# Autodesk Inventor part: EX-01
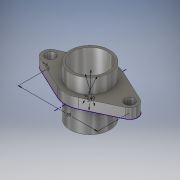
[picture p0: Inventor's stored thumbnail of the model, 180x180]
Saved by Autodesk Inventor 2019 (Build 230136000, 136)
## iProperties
Created: 2018-08
Part Number: EX-01
Material: Nickel-Copper Alloy 400
Description: 123456
Document SubType Name: Modeling
Designer: Power User
Mass: 162915 g
Surface Area: 10619 cm^2
Volume: 18450.2 cm^3
Density: 8.83 g/cm^3
Appearance: Chrome - Polished
Title: GEAR
Author: Power User
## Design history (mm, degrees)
sketch "Sketch6"
  geometry: L1 (0, 36.463)-(0, -36.463); L2 (-43.4, 7.242)-(-10.625, 22.63); L3 (-40, 0)-(40, 0); L4 (-43.4, -7.242)-(-10.625, -22.63); L5 (10.625, 22.63)-(43.4, 7.242); L6 (10.625, -22.63)-(43.4, -7.242); C1 r 17.5 at (0, 0); C2 r 20 at (0, 0); C3 r 5 at (-40, 0); C4 r 5 at (40, 0); A1 r 25 centre (0, 0) between (-10.625, 22.63) and (-10.625, -22.63); A2 r 8 centre (-40, 0) between (-43.4, 7.242) and (-43.4, -7.242); A3 r 8 centre (40, 0) between (43.4, 7.242) and (43.4, -7.242); 2 further points
  constraints: 12 end point, 8 point on circle, 8 tangent, 7 centre point, 6 coincident, 2 equal radius, 2 horizontal alignment, 1 horizontal, 1 midpoint, 1 symmetric about line, 1 vertical
  dimensions: "d49" = 35 diameter of C1; "d50" = 40 diameter of C2; "d51" = 50 diameter of A1; "d52" = 5 radius of C3; "d54" = 80 distance of C4.centre C3.centre; "d55" = 8 radius of A2
extrude "Extrusion5" new body sketch "Sketch6" distance "d57" = 10; taper "d58" = 0 deg
extrude "Extrusion6" new body sketch "Sketch6" stored distance "d59" = 50; taper "d60" = 0 deg
body "Solid2"
body "Solid3"
